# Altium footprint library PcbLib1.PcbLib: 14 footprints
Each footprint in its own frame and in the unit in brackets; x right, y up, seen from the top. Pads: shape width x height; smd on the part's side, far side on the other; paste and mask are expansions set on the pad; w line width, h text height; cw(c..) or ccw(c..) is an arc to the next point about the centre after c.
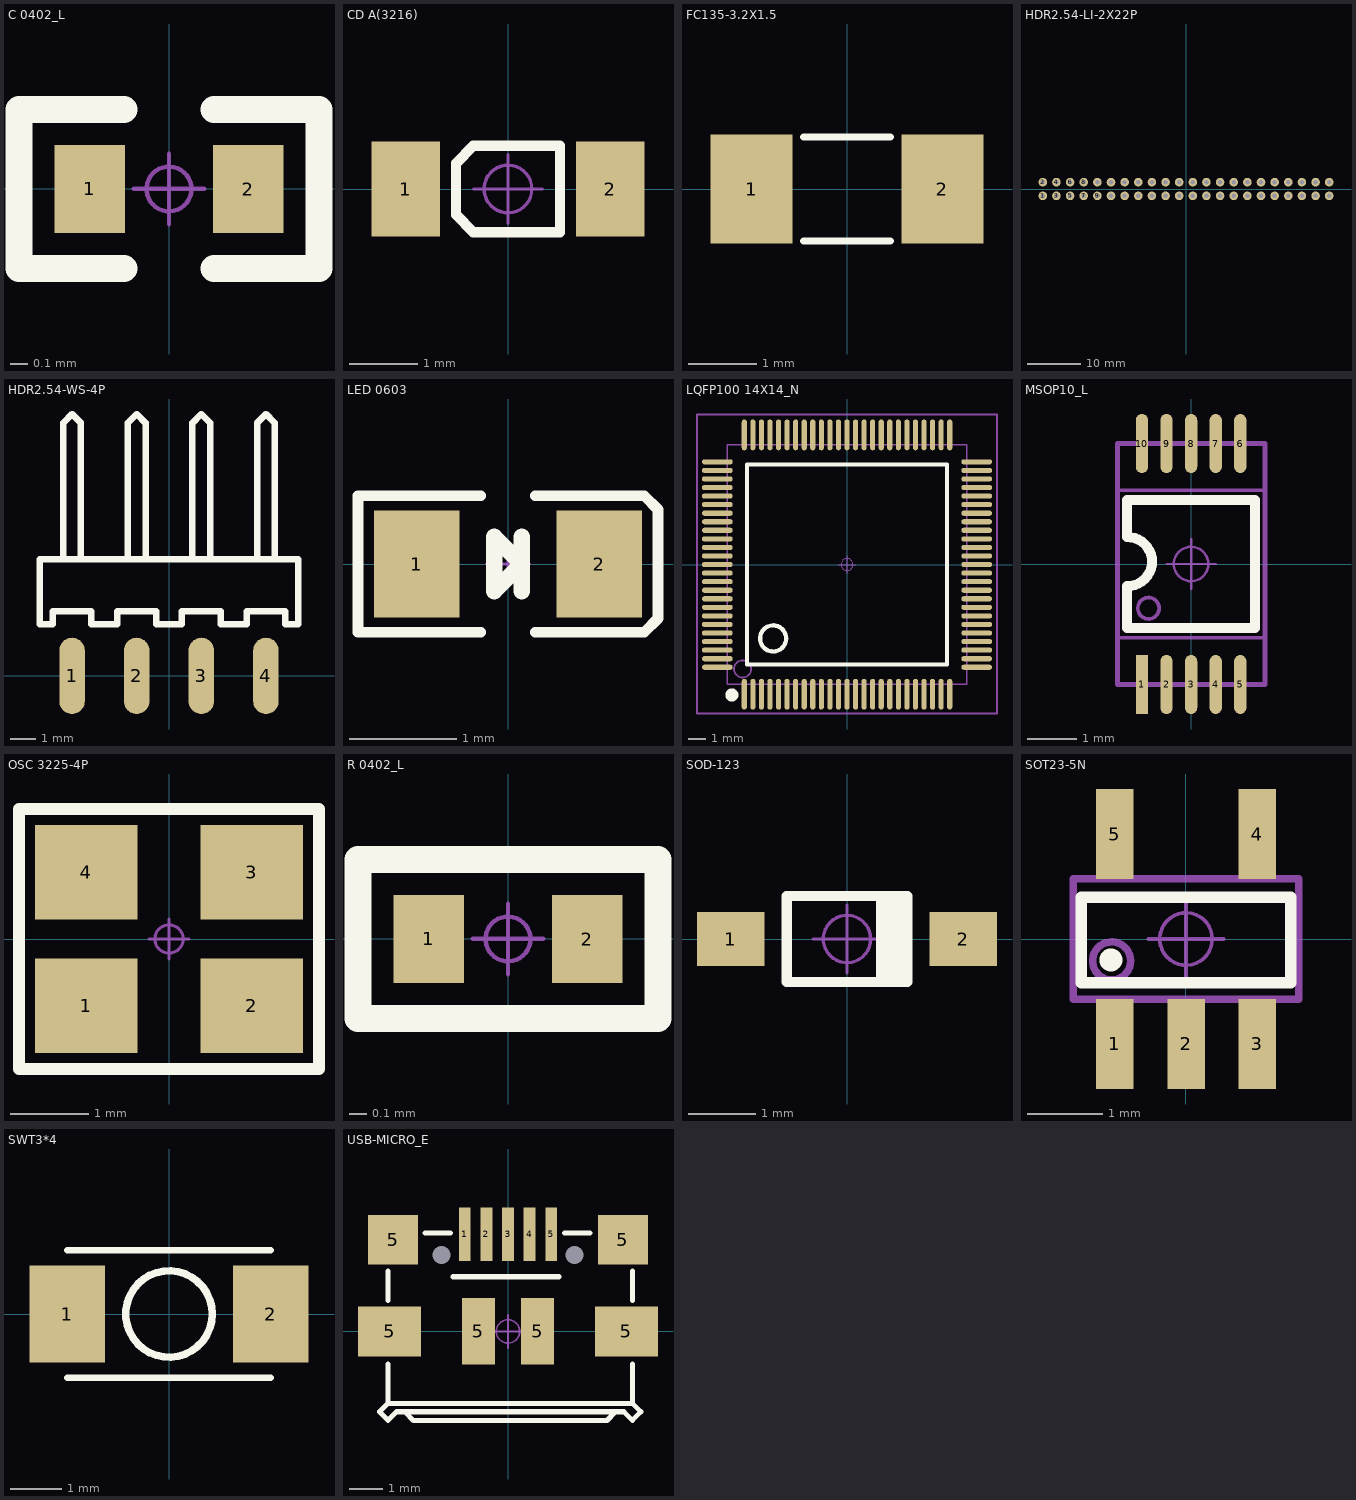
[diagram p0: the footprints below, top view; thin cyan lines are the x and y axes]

## C 0402_L [mm] "无极性贴片电容"
pads (2):
  rect 0.4x0.5 smd: 1(-0.45,0) 2(0.45,0)
Top Overlay:
  lines w0.152: -0.254,-0.45 -0.85,-0.45 ; -0.254,0.45 -0.85,0.45 -0.85,-0.45 ; 0.254,-0.45 0.85,-0.45 0.85,0.45 0.254,0.45 ; -0.85,-0.45 -0.85,-0.45
Mechanical 15:
  circle w0.025: c0,0 r0.127
  lines w0.025: -0.2,0 0.2,0 ; 0,-0.2 0,0.2
3D body "C 0402.STEP": height 0.53, standoff 0.01, extent -0.5,-0.26 0.5,0.26

## CD A(3216) [mm] "长3.2mm，宽1.6mm，厚1.6mm"
pads (2):
  rect 1x1.4 smd: 1(-1.5,0) 2(1.5,0)
Top Overlay:
  lines w0.152: -0.762,-0.381 -0.508,-0.635 0.762,-0.635 0.762,0.635 -0.508,0.635 -0.762,0.381 -0.762,-0.381
Mechanical 15:
  circle w0.05: c0,0 r0.35
  lines w0.05: -0.5,0 0.5,0 ; 0,-0.5 0,0.5
3D body "CD A(3216).STEP": height 1.6, standoff -0.01, extent -1.6,-0.8 1.6,0.8

## FC135-3.2X1.5 [mm] "晶振"
pads (2):
  rect 1.2x1.6 smd: 1(-1.4,0) 2(1.4,0)
Top Overlay:
  lines w0.102: -0.635,-0.762 0.635,-0.762 ; -0.635,0.762 0.635,0.762
3D body "User Library-ABS07.STEP": height 0.91, standoff 0, extent -1.61,-0.76 1.61,0.76

## HDR2.54-LI-2X22P [mm] "双排排针，20x2脚"
pads (44):
  round 1.6 hole 0.9: 1(-26.67,-1.27) 2(-26.67,1.27) 3(-24.13,-1.27) 4(-24.13,1.27) 5(-21.59,-1.27) 6(-21.59,1.27) 7(-19.05,-1.27) 8(-19.05,1.27) 9(-16.51,-1.27) 10(-16.51,1.27) 11(-13.97,-1.27) 12(-13.97,1.27) 13(-11.43,-1.27) 14(-11.43,1.27) 15(-8.89,-1.27) 16(-8.89,1.27) 17(-6.35,-1.27) 18(-6.35,1.27) 19(-3.81,-1.27) 20(-3.81,1.27) 21(-1.27,-1.27) 22(-1.27,1.27) 23(1.27,-1.27) 24(1.27,1.27) 25(3.81,-1.27) 26(3.81,1.27) 27(6.35,-1.27) 28(6.35,1.27) 29(8.89,-1.27) 30(8.89,1.27) 31(11.43,-1.27) 32(11.43,1.27) 33(13.97,-1.27) 34(13.97,1.27) 35(16.51,-1.27) 36(16.51,1.27) 37(19.05,-1.27) 38(19.05,1.27) 39(21.59,-1.27) 40(21.59,1.27) 41(24.13,-1.27) 42(24.13,1.27) 43(26.67,-1.27) 44(26.67,1.27)
Bottom Overlay:
  lines w0.2: -27.94,-2.159 -27.94,2.159
  lines w0.203: -27.94,-2.159 -27.559,-2.54 27.559,-2.54 27.94,-2.159 27.94,2.159 27.559,2.54 -27.559,2.54 -27.94,2.159 ; -27.94,0 27.94,0 ; -25.4,-2.54 -25.4,2.54 ; -22.86,-2.54 -22.86,2.54 ; -20.32,-2.54 -20.32,2.54 ; -17.78,-2.54 -17.78,2.54 ; -15.24,-2.54 -15.24,2.54 ; -12.7,-2.54 -12.7,2.54 ; -10.16,-2.54 -10.16,2.54 ; -7.62,-2.54 -7.62,2.54 ; -5.08,-2.54 -5.08,2.54 ; -2.54,-2.54 -2.54,2.54 ; 0,-2.54 0,2.54 ; 2.54,-2.54 2.54,2.54 ; 5.08,-2.54 5.08,2.54 ; 7.62,-2.54 7.62,2.54 ; 10.16,-2.54 10.16,2.54 ; 12.7,-2.54 12.7,2.54 ; 15.24,-2.54 15.24,2.54 ; 17.78,-2.54 17.78,2.54 ; 20.32,-2.54 20.32,2.54 ; 22.86,-2.54 22.86,2.54 ; 25.4,-2.54 25.4,2.54
3D body "HDR2.54-1x2P.STEP": height 8.5, standoff -3, extent 25.4,-2.54 27.94,2.54
3D body "HDR2.54-1x2P.STEP": height 8.5, standoff -3, extent 22.86,-2.54 25.4,2.54
3D body "HDR2.54-1x2P.STEP": height 8.5, standoff -3, extent 20.32,-2.54 22.86,2.54
3D body "HDR2.54-1x2P.STEP": height 8.5, standoff -3, extent 17.78,-2.54 20.32,2.54
3D body "HDR2.54-1x2P.STEP": height 8.5, standoff -3, extent 15.24,-2.54 17.78,2.54
3D body "HDR2.54-1x2P.STEP": height 8.5, standoff -3, extent 12.7,-2.54 15.24,2.54
3D body "HDR2.54-1x2P.STEP": height 8.5, standoff -3, extent 10.16,-2.54 12.7,2.54
3D body "HDR2.54-1x2P.STEP": height 8.5, standoff -3, extent 7.62,-2.54 10.16,2.54
3D body "HDR2.54-1x2P.STEP": height 8.5, standoff -3, extent 5.08,-2.54 7.62,2.54
3D body "HDR2.54-1x2P.STEP": height 8.5, standoff -3, extent 2.54,-2.54 5.08,2.54
3D body "HDR2.54-1x2P.STEP": height 8.5, standoff -3, extent 0,-2.54 2.54,2.54
3D body "HDR2.54-1x2P.STEP": height 8.5, standoff -3, extent -2.54,-2.54 0,2.54
3D body "HDR2.54-1x2P.STEP": height 8.5, standoff -3, extent -5.08,-2.54 -2.54,2.54
3D body "HDR2.54-1x2P.STEP": height 8.5, standoff -3, extent -7.62,-2.54 -5.08,2.54
3D body "HDR2.54-1x2P.STEP": height 8.5, standoff -3, extent -10.16,-2.54 -7.62,2.54
3D body "HDR2.54-1x2P.STEP": height 8.5, standoff -3, extent -12.7,-2.54 -10.16,2.54
3D body "HDR2.54-1x2P.STEP": height 8.5, standoff -3, extent -15.24,-2.54 -12.7,2.54
3D body "HDR2.54-1x2P.STEP": height 8.5, standoff -3, extent -17.78,-2.54 -15.24,2.54
3D body "HDR2.54-1x2P.STEP": height 8.5, standoff -3, extent -20.32,-2.54 -17.78,2.54
3D body "HDR2.54-1x2P.STEP": height 8.5, standoff -3, extent -22.86,-2.54 -20.32,2.54
3D body "HDR2.54-1x2P.STEP": height 8.5, standoff -3, extent -25.4,-2.54 -22.86,2.54
3D body "HDR2.54-1x2P.STEP": height 8.5, standoff -3, extent -27.94,-2.54 -25.4,2.54

## HDR2.54-WS-4P [mm] "4P卧式贴片排针2.54"
pads (4):
  oval 1x3 smd: 1(-3.81,0) 2(-1.27,0) 3(1.27,0) 4(3.81,0)
Top Overlay:
  lines w0.254: -4.16,4.572 -4.16,9.8 -4.16,9.937 -3.81,10.287 -3.46,9.937 -3.46,9.8 -3.46,4.572 ; -1.62,4.572 -1.62,9.8 -1.62,9.937 -1.27,10.287 -0.92,9.937 -0.92,9.8 -0.92,4.572 ; 0.92,4.572 0.92,9.8 0.92,9.937 1.27,10.287 1.62,9.937 1.62,9.8 1.62,4.572 ; 3.46,4.572 3.46,9.8 3.46,9.937 3.81,10.287 4.16,9.937 4.16,9.8 4.16,4.572 ; -5.08,2.032 -5.08,4.572 -2.54,4.572 0,4.572 2.54,4.572 5.08,4.572 5.08,2.032 4.572,2.032 4.572,2.54 4.318,2.54 3.048,2.54 3.048,2.032 2.54,2.032 2.032,2.032 2.032,2.54 1.778,2.54 0.508,2.54 0.508,2.032 0,2.032 -0.508,2.032 -0.508,2.54 -0.762,2.54 -2.032,2.54 -2.032,2.032 -2.54,2.032 -3.048,2.032 -3.048,2.54 -3.302,2.54 -4.572,2.54 -4.572,2.032 -5.08,2.032
3D body "HDR2.54 S-W-1P.STEP": height 2.54, standoff -0.01, extent -5.08,-0.76 -2.54,10.34
3D body "HDR2.54 S-W-1P.STEP": height 2.54, standoff -0.01, extent -2.54,-0.76 0,10.34
3D body "HDR2.54 S-W-1P.STEP": height 2.54, standoff -0.01, extent 0,-0.76 2.54,10.34
3D body "HDR2.54 S-W-1P.STEP": height 2.54, standoff -0.01, extent 2.54,-0.76 5.08,10.34

## LED 0603 [mm] "贴片带丝印"
height 0.6
pads (2):
  rect 0.8x1 smd: 1(-0.85,0) 2(0.85,0)
Top Overlay:
  lines w0.1: -0.254,-0.635 -1.397,-0.635 -1.397,0.635 -0.254,0.635 ; 0.254,-0.635 1.27,-0.635 1.397,-0.508 1.397,0.508 1.27,0.635 0.254,0.635
  lines w0.152: 0.127,-0.254 0.127,0.254 ; -0.127,-0.254 -0.127,0.254 0.127,0 -0.127,-0.254
Mechanical 15:
  circle w0.025: c0,0 r0.127
  lines w0.025: -0.2,0 0.2,0 ; 0,-0.2 0,0.2
3D body "LED 0603-W.STEP": height 0.47, standoff 0, extent -0.8,-0.401 0.8,0.401
3D body "LED 0603玻璃罩.STEP": height 0.61, standoff 0.21, extent -0.6,-0.4 0.6,0.4

## LQFP100 14X14_N [mm] "100脚，体宽14x14mm，脚距0.5mm"
height 1.6
pads (100):
  oval 0.3x1.8 smd: 1(-6,-7.575) 2(-5.5,-7.575) 3(-5,-7.575) 4(-4.5,-7.575) 5(-4,-7.575) 6(-3.5,-7.575) 7(-3,-7.575) 8(-2.5,-7.575) 9(-2,-7.575) 10(-1.5,-7.575) 11(-1,-7.575) 12(-0.5,-7.575) 13(0,-7.575) 14(0.5,-7.575) 15(1,-7.575) 16(1.5,-7.575) 17(2,-7.575) 18(2.5,-7.575) 19(3,-7.575) 20(3.5,-7.575) 21(4,-7.575) 22(4.5,-7.575) 23(5,-7.575) 24(5.5,-7.575) 25(6,-7.575) 51(6,7.575) 52(5.5,7.575) 53(5,7.575) 54(4.5,7.575) 55(4,7.575) 56(3.5,7.575) 57(3,7.575) 58(2.5,7.575) 59(2,7.575) 60(1.5,7.575) 61(1,7.575) 62(0.5,7.575) 63(0,7.575) 64(-0.5,7.575) 65(-1,7.575) 66(-1.5,7.575) 67(-2,7.575) 68(-2.5,7.575) 69(-3,7.575) 70(-3.5,7.575) 71(-4,7.575) 72(-4.5,7.575) 73(-5,7.575) 74(-5.5,7.575) 75(-6,7.575)
  oval 1.8x0.3 smd: 26(7.576,-6) 27(7.576,-5.5) 28(7.576,-5) 29(7.576,-4.5) 30(7.576,-4) 31(7.576,-3.5) 32(7.576,-3) 33(7.576,-2.5) 34(7.576,-2) 35(7.576,-1.5) 36(7.576,-1) 37(7.576,-0.5) 38(7.576,0) 39(7.576,0.5) 40(7.576,1) 41(7.576,1.5) 42(7.576,2) 43(7.576,2.5) 44(7.576,3) 45(7.576,3.5) 46(7.576,4) 47(7.576,4.5) 48(7.576,5) 49(7.576,5.5) 50(7.576,6) 76(-7.575,6) 77(-7.575,5.5) 78(-7.575,5) 79(-7.575,4.5) 80(-7.575,4) 81(-7.575,3.5) 82(-7.575,3) 83(-7.575,2.5) 84(-7.575,2) 85(-7.575,1.5) 86(-7.575,1) 87(-7.575,0.5) 88(-7.575,0) 89(-7.575,-0.5) 90(-7.575,-1) 91(-7.575,-1.5) 92(-7.575,-2) 93(-7.575,-2.5) 94(-7.575,-3) 95(-7.575,-3.5) 96(-7.575,-4) 97(-7.575,-4.5) 98(-7.575,-5) 99(-7.575,-5.5) 100(-7.575,-6)
Top Overlay:
  circle w0.254: c-4.318,-4.318 r0.762
  circle w0.381: c-6.731,-7.62 r0.191
  lines w0.254: -5.842,-5.842 5.842,-5.842 5.842,5.842 -5.842,5.842 -5.842,-5.842
Mechanical 13:
  circle w0.1: c-6.1,-6.1 r0.5
  lines w0.1: -7,-7 -7,7 7,7 7,-7 -7,-7
Mechanical 15:
  circle w0.05: c0,0 r0.35
  lines w0.05: -0.5,0 0.5,0 ; 0,-0.5 0,0.5
  lines w0.1: -8.763,-8.7 -8.763,8.763 8.763,8.763 8.763,-8.7 -8.763,-8.7
3D body "LQFP100-14x14.STEP": height 1.45, standoff -0.01, extent -8.003,-8.003 8.003,8.003

## MSOP10_L [mm] "塑封体长3mm，宽3mm，脚距0.5"
pads (10):
  rect 0.25x1.2 smd: 1(-1,-2.45)
  oval 0.25x1.2 smd: 2(-0.5,-2.45) 3(0,-2.45) 4(0.5,-2.45) 5(1,-2.45) 6(1,2.45) 7(0.5,2.45) 8(0,2.45) 9(-0.5,2.45) 10(-1,2.45)
Top Overlay:
  lines w0.2: -1.3,-1.3 1.3,-1.3 1.3,1.3 -1.3,1.3
  lines w0.203: -1.3,-1.3 -1.3,-0.46 ; -1.3,-0.45 ccw(c-1.3,0.058) -0.792,0.058 ; -1.3,0.55 cw(c-1.3,0.042) -0.792,0.042 ; -1.3,0.556 -1.3,1.3
Mechanical 13:
  circle w0.076: c-0.867,-0.9 r0.217
  lines w0.076: -1.5,-1.5 1.5,-1.5 1.5,1.5 -1.5,1.5 -1.5,-1.5
Mechanical 15:
  circle w0.05: c0,0 r0.35
  lines w0.05: -0.5,0 0.5,0 ; 0,-0.5 0,0.5
  lines w0.1: -1.5,-2.45 -1.5,2.45 1.5,2.45 1.5,-2.45 -1.5,-2.45
3D body "MSOP-10.STEP": height 0.95, standoff 0, extent -1.5,-2.45 1.5,2.45

## OSC 3225-4P [mm] "3.2*2.5*0.7mm(长宽高)"
pads (4):
  rect 1.3x1.2 smd: 1(-1.05,-0.85) 2(1.05,-0.85) 3(1.05,0.85) 4(-1.05,0.85)
Top Overlay:
  lines w0.152: -1.905,-1.651 -1.905,1.651 1.905,1.651 1.905,-1.651 -1.905,-1.651
Mechanical 15:
  circle w0.04: c0,0 r0.18
  lines w0.04: -0.254,0 0.254,0 ; 0,-0.254 0,0.254
3D body "OSC 3225-4.STEP": height 0.7, standoff -0.02, extent -1.6,-1.25 1.6,1.25

## R 0402_L [mm] "1/16W贴片电阻"
pads (2):
  rect 0.4x0.5 smd: 1(-0.45,0) 2(0.45,0)
Top Overlay:
  lines w0.152: -0.85,-0.45 -0.85,0.45 0.85,0.45 0.85,-0.45 -0.85,-0.45 ; -0.85,-0.45 -0.85,-0.45
Mechanical 15:
  circle w0.025: c0,0 r0.127
  lines w0.025: -0.2,0 0.2,0 ; 0,-0.2 0,0.2
3D body "R 0402.STEP": height 0.3, standoff 0, extent -0.5,-0.25 0.5,0.25

## SOD-123 [mm] "2.7x1.6X1.1mm（长宽高，不包括引脚）"
pads (2):
  rect 1x0.8 smd: 1(-1.714,0) 2(1.714,0)
Top Overlay:
  lines w0.152: 0.508,-0.635 0.508,0.635 ; 0.635,-0.635 0.635,0.635 ; 0.762,-0.635 0.762,0.635 ; -0.889,-0.635 -0.889,0.635 0.889,0.635 0.889,-0.635 -0.889,-0.635
Mechanical 15:
  circle w0.05: c0,0 r0.35
  lines w0.05: -0.5,0 0.5,0 ; 0,-0.5 0,0.5
3D body "SOD-123.STEP": height 1.22, standoff 0, extent -1.85,-0.8 1.85,0.8

## SOT23-5N [mm] "3x1.6x1.1mm(长宽高)"
pads (5):
  rect 0.5x1.2 smd: 1(-0.95,-1.4) 2(0,-1.4) 3(0.95,-1.4) 4(0.95,1.4) 5(-0.95,1.4)
Top Overlay:
  circle w0.254: c-1.001,-0.279 r0.025
  lines w0.152: -1.397,-0.584 1.397,-0.584 1.397,0.559 -1.397,0.559 -1.397,-0.584
Mechanical 13:
  circle w0.1: c-0.992,-0.292 r0.254
  lines w0.1: -1.5,-0.8 1.5,-0.8 1.5,0.8 -1.5,0.8 -1.5,-0.8
Mechanical 15:
  circle w0.05: c0,0 r0.35
  lines w0.05: -0.5,0 0.5,0 ; 0,-0.5 0,0.5
3D body "SOT-23-5.STEP": height 1.2, standoff 0, extent -1.45,-1.4 1.45,1.4

## SWT3*4 [mm]
pads (2):
  rect 1.48x1.9 smd: 1(-2,0) 2(2,0)
Top Overlay:
  circle w0.15: c0,0 r0.85
  lines w0.127: -2,-1.25 2,-1.25 ; -2,1.25 2,1.25
3D body "User Library-Pushbutton3x4x2.step": height 2, standoff 0, extent -2.45,-1.45 2.45,1.45

## USB-MICRO_E [mm] "micro型USB ，5.9*8.2*2.5mm"
pads (13):
  round 0 hole 0.54 unplated: 0(-2,2.294) 0(2,2.294)
  rect 0.35x1.6 smd: 1(-1.295,2.921) 2(-0.648,2.921) 3(0,2.921) 4(0.648,2.921) 5(1.295,2.921)
  rect 1.9x1.5 smd: 5(-3.556,0) 5(3.556,0)
  rect 1.5x1.5 smd: 5(-3.454,2.754) 5(3.454,2.754)
  rect 1x2 smd: 5(-0.889,0.01) 5(0.889,0.01)
Top Overlay:
  lines w0.15: -2.489,2.959 -1.727,2.959 ; 1.702,2.959 2.464,2.959
  lines w0.152: -3.607,-0.978 -3.607,-2.159 ; -3.607,0.927 -3.607,1.816 ; -1.645,1.642 1.53,1.642 ; 3.734,-0.978 3.734,-2.159 ; 3.734,0.927 3.734,1.816 ; -3.607,-2.159 -3.861,-2.413 -3.607,-2.667 -3.353,-2.413 -3.099,-2.413 ; -3.607,-2.159 3.734,-2.159 ; -3.099,-2.413 3.226,-2.413 ; -3.099,-2.413 -2.845,-2.673 2.972,-2.673 3.226,-2.413 ; 3.226,-2.413 3.48,-2.413 3.734,-2.667 3.988,-2.413 3.734,-2.159
Mechanical 15:
  circle w0.05: c0,0 r0.35
  lines w0.05: -0.5,0 0.5,0 ; 0,-0.5 0,0.5
3D body "USB micro_E.STEP": height 2.8, standoff -0.55, extent -4.001,-2.716 4.001,3.359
